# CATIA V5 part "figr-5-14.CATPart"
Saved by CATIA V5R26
Part number: Part1
Bounding box of the stored display mesh (mm): x 0 to 150, y -70 to 70, z -150 to 69.804
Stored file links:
  D:\_Deepak\CATIA\CATIA V5-6R2016_Deepak\Resources\Part files\Partfiles\c05_catia_v5_6r2016_prt\figr-5-14.CATPart
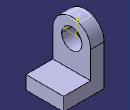
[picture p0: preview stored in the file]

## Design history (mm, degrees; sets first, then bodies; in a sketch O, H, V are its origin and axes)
Set1
  Plane1: type Offset, RefPlane face of Pad1, Offset -18, reversed
  Plane2: type Tangent, Support face of Pad1, RefPoint Sketch3
Body1 (main body)
  Sketch1 on yz-plane, origin (0, 0, 0), H (0, 1, 0), V (0, 0, 1)
    arc A1 centre (0, 0) radius 70 from (70, 0) to (-70, 0) ccw
    point P1 (70, 0)
    point P2 (-70, 0)
    line L1 (-70, 0) -> (-70, -150)
    line L2 (-70, -150) -> (70, -150)
    line L3 (70, -150) -> (70, 0)
    circle A2 centre (0, 0) radius 37.5
    radius A1 = 70
    radius A2 = 37.5
    distance O L2 = 150
    coincidence: P1 H, P2 H
    tangency: L1 A1, L3 A1
    horizontal: L2 H
  Pad1: profile Sketch1, direction (1, 0, 0), length 50
  Sketch2 on face of Pad1, origin (50, 0, 0), H (0, 1, 0), V (0, 0, 1)
    line L1 (-70, -150) -> (70, -150)
    line L2 (70, -150) -> (70, -100)
    line L3 (70, -100) -> (-70, -100)
    line L4 (-70, -100) -> (-70, -150)
    reference projected line E1 (-70, -150) -> (70, -150) from edge [face of Pad1 | face of Pad1]
    reference projected line E2 (-70, 0) -> (-70, -150) from edge [face of Pad1 | face of Pad1]
    reference projected line E3 (70, -150) -> (70, 0) from edge [face of Pad1 | face of Pad1]
    length L2 = 50
    horizontal: L1 H, L3 H
    vertical: L2 V, L4 V
    coincidence: L1 E1, E2 L4, L2 E3
  Pad2: profile Sketch2, direction (1, 0, 0), length 100
  Sketch3 on Plane1, origin (32, 0, 0), H (0, -1, 0), V (0, 0, 1)
    point P1 (-7.2142, 69.6273)
    reference projected arc E1 centre (0, 0) radius 70 from (70, 0) to (-70, 0) ccw from edge [face of Pad1 | face of Pad1]
    coincidence: P1 E1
